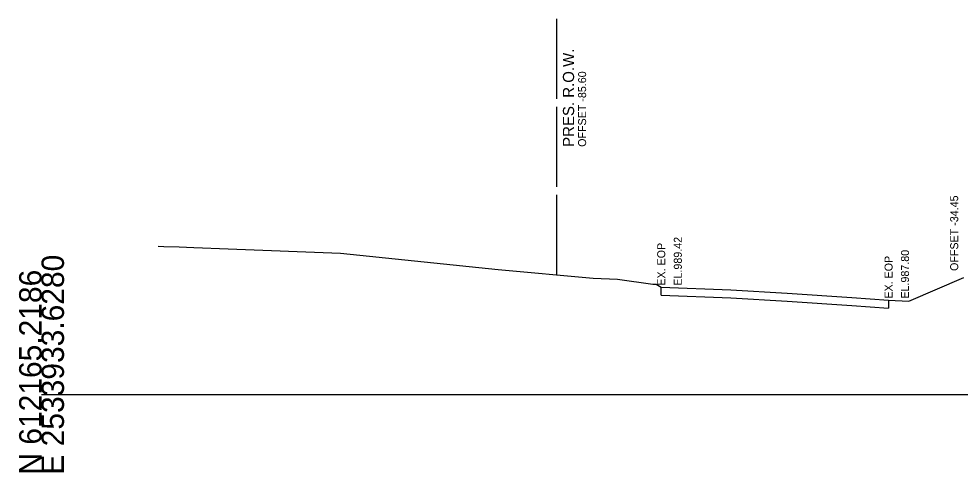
# Model space of a CAD drawing. Extents: x -120 to 2876, y -25 to 8560.
# Drawn here: x 1297.2 to 1414.8, y 1490.3 to 1547 of the extents above; entities that cross this region are included whole.
import ezdxf

# ---------------------------------------------------------------- set-up
doc = ezdxf.new("R2010")
doc.units = 0
for name, color, linetype in [('DESIGN - SHEET - Light Grid', 7, 'Continuous'), ('DESIGN - TYPICAL - Slope Tie Text', 7, 'Continuous'), ('SURVEY - GROUND - Existing Pavement Layer', 7, 'Continuous'), ('SURVEY - GROUND - Existing Pavement Text', 7, 'Continuous'), ('SURVEY - GROUND - Top of Ground', 7, 'Continuous'), ('SURVEY - PROPERTY - ROW Lines', 7, 'Continuous'), ('SURVEY - PROPERTY - ROW Lines Text', 7, 'Continuous')]:
    doc.layers.add(name, color=color, linetype=linetype)

msp = doc.modelspace()

# ---------------------------------------------------------------- linework, layer by layer
at = {"layer": 'DESIGN - SHEET - Light Grid'}
msp.add_line((1300, 1500), (1450, 1500), dxfattribs=at)
at = {"layer": 'SURVEY - GROUND - Existing Pavement Layer'}
for p, q in [((1377.44, 1512.42), (1377.44, 1513.42)), ((1377.44, 1512.42), (1386.12, 1512.09)), ((1386.12, 1512.09), (1393.18, 1511.69)), ((1393.18, 1511.69), (1401.26, 1511.12)), ((1405.85, 1511.8), (1405.85, 1510.8)), ((1401.26, 1511.12), (1405.85, 1510.8))]:
    msp.add_line(p, q, dxfattribs=at)
at = {"layer": 'SURVEY - GROUND - Top of Ground'}
msp.add_lwpolyline([(1314.59, 1518.54), (1315.27, 1518.52), (1317.2, 1518.46), (1319.04, 1518.38), (1323.33, 1518.22), (1337.37, 1517.67), (1357.08, 1515.65), (1368.93, 1514.55), (1371.96, 1514.45), (1376.39, 1513.79), (1376.79, 1513.79), (1377.44, 1513.42), (1386.12, 1513.09), (1393.18, 1512.69), (1401.26, 1512.12), (1405.85, 1511.8), (1408.36, 1511.67), (1415.27, 1514.64)], dxfattribs=at)
at = {"layer": 'SURVEY - PROPERTY - ROW Lines'}
for p, q in [((1364.4, 1536.97), (1364.4, 1546.97)), ((1364.4, 1525.97), (1364.4, 1535.97)), ((1364.4, 1514.97), (1364.4, 1524.97))]:
    msp.add_line(p, q, dxfattribs=at)

# ---------------------------------------------------------------- texts
at = {"layer": 'DESIGN - SHEET - Light Grid'}
for s, p in [('E 2533933.6280', (1302.8, 1490)), ('N 612165.2186', (1300, 1490))]:
    msp.add_text(s, height=2.8, rotation=90, dxfattribs=at).set_placement(p)
at = {"layer": 'DESIGN - TYPICAL - Slope Tie Text'}
msp.add_text('OFFSET -34.45', height=1, rotation=90, dxfattribs=at).set_placement((1414.55, 1515.46))
at = {"layer": 'SURVEY - GROUND - Existing Pavement Text'}
for s, p in [('EX. EOP', (1377.94, 1513.62)), ('EL.989.42', (1380.01, 1513.62)), ('EL.987.80', (1408.4, 1512)), ('EX. EOP', (1406.35, 1512))]:
    msp.add_text(s, height=1, rotation=90, dxfattribs=at).set_placement(p)
at = {"layer": 'SURVEY - PROPERTY - ROW Lines Text'}
for s, height, p in [('PRES. R.O.W.', 1.4, (1366.55, 1530.97)), ('OFFSET -85.60', 1, (1368.05, 1530.97))]:
    msp.add_text(s, height=height, rotation=90, dxfattribs=at).set_placement(p)

doc.saveas('drawing.dxf')
